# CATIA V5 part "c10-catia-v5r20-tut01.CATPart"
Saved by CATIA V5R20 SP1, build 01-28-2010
Part number: c10tut1
Bounding box of the stored display mesh (mm): x -88.579 to 88.579, y -88.579 to 151.815, z -258.54 to 20
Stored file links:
  D:\v5_r20\psrt_files_downloaded\c10\c10-catia-v5r20-tut01.CATPart
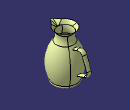
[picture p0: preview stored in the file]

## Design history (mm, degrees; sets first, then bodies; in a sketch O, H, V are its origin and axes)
Body1 (main body)
  Sketch1 on xy-plane, origin (0, 0, 0), H (1, 0, 0), V (0, 1, 0)
    circle A1 centre (0, 0) radius 45
    point P1 (-5, -44.7214)
    point P2 (5, -44.7214)
    radius A1 = 45
    distance P2 P1 = 10
    distance V P1 = 5
    coincidence: P1 A1, P2 A1
  Plane1: type Offset, RefPlane xy-plane, Offset 20
  Sketch2 on Plane1, origin (0, 0, 20), H (1, 0, 0), V (0, 1, 0)
    arc A1 centre (0, 0) radius 60 from (30.5123, -51.6623) to (-30.5123, -51.6623) ccw
    line L1 (-30.5123, -51.6623) -> (-7.9335, -81.0876)
    point P1 (0, -91.4268)
    line L2 (7.9335, -81.0876) -> (30.5123, -51.6623)
    arc A2 centre (0, -75) radius 10 from (-7.9335, -81.0876) to (7.9335, -81.0876) ccw
    point P4 (0, -75)
    radius A1 = 60
    angle L1 L2 = 75
    radius A2 = 10
    distance P4 H = 75
    coincidence: P1 V, L1 P1, L2 P1, P4 V
    tangency: A2 L1, A2 L2
  Line1: type PtPt, FirstPoint Sketch1.P2, SecondPoint vertex [element of Sketch2 | element of Sketch2]
  Loft1: Sections (Sketch1.A1; Sketch2), Guides Line1
  Sketch3 on yz-plane, origin (0, 0, 0), H (0, 1, 0), V (0, 0, 1)
    axis line L1 (0, 49.2285) -> (0, -442.7765)
    point P1 (0, 49.2285)
    arc A1 centre (-106.3963, -163.4174) radius 195 from (70, -246.5398) to (52.2275, -50) ccw
    point P4 (70, -246.5398)
    point P5 (52.2275, -50)
    arc A2 centre (96.9675, -18.0105) radius 55 from (45, 0) to (52.2275, -50) ccw
    point P7 (52.2275, -50)
    point P8 (45, 0)
    line L2 (54, -258.5398) -> (64, -258.5398)
    point P9 (54, -258.5398)
    point P10 (64, -258.5398)
    arc A3 centre (64, -251.0398) radius 7.5 from (64, -258.5398) to (70, -246.5398) ccw
    point P12 (64, -258.5398)
    arc A4 centre (0, -425) radius 175 from (54, -258.5398) to (0, -250) ccw
    point P13 (0, -425)
    point P14 (0, -250)
    radius A2 = 55
    radius A1 = 195
    radius A3 = 7.5
    length L2 = 10
    radius A4 = 175
    distance P14 H = 250
    "Radius" P4 L1 = 70
    "Radius" P9 L1 = 54
    "Radius" P8 L1 = 45
    distance P5 H = 50
    coincidence: P1 V, P7 A1, P7 P5, P10 P12, P13 L1, P14 L1, P8 H
    tangency: A2 A1, A3 L2
    vertical: L1 V
    horizontal: L2 H
  Revol1: Element1 Sketch3, Angle1 360
  Sketch4 on yz-plane, origin (0, 0, 0), H (0, 1, 0), V (0, 0, 1)
    point P1 (35.2741, -74.8693)
    line L1 (35.2741, -74.8693) -> (86.9572, -56.0582)
    line L2 (119, -71) -> (145.5066, -143.8262)
    line L3 (130.5647, -175.869) -> (63.8466, -200.1524)
    arc A1 centre (95.5077, -79.5505) radius 25 from (86.9572, -56.0582) to (119, -71) cw
    point P4 (119, -71)
    arc A2 centre (122.0142, -152.3767) radius 25 from (145.5066, -143.8262) to (130.5647, -175.869) cw
    radius A1 = 25
    radius A2 = 25
    length L2 = 77.5
    length L1 = 55
    angle H L1 = 20
    distance P4 V = 119
    distance P4 H = 71
    length L3 = 71
    perpendicularity: L2 L1
    parallelism: L3 L1
    tangency: A1 L1, A1 L2, A2 L2, A2 L3
  Plane2: type Normal, Curve Sketch4, RefPoint Sketch4.P1
  Sketch5 on Plane2, origin (0, 7.0853, 2.5788), H (1, 0, 0), V (0, -0.342, 0.9397)
    point P1 (0, -82.4186)
    ellipse A1 centre (0, -82.4186) semi-axes 12.5, 5 rotation 0
    reference projected point E1 (0, -82.4186) from Sketch4.P1
    "Radius" A1 = 5
    "Radius" A1 = 12.5
    horizontal: A1 H
    coincidence: P1 E1
  Sweep1: type Unspec, Profile Sketch5, Guide Sketch4
  Split1: ToCut Sweep1, Cutting Revol1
